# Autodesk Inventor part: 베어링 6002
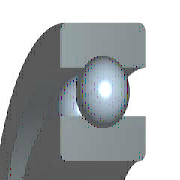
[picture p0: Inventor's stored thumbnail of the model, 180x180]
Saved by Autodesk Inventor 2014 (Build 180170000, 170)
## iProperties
Created: 2012-02
Part Number: 베어링 6002
Material: 강철, 연강
Description: 깊은 그루브 볼 베어링
Document SubType Name: Modeling
Standard: KS B 2023
Designer: mduedu
Standards Organization: KS
Language: ko-KR
Size Designation: 6002 - 15 x 32 x 9
Categories: <MemberInstance><Categories><Category DisplayName="샤프트 부품" InternalName="7f7aeb1f-a693-4053-b835-cee3144e0d98" Mnemonic="SHFT"><Category DisplayName="베어링" Inter
Density: 7.86 g/cm^3
Mass: 29.8124 g
Surface Area: 39.9079 cm^2
Volume: 3.79293 cm^3
Appearance: Pink
IsCustomPart: 1
Author: mduedu
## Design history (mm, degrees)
sketch "스케치" dims "d0" = 4.42 (= -0.26 x WD + 0.26 x BD)
  geometry: L1 (2.29, 11.75)-(6.71, 11.75); L2 (4.5, 11.75)-(4.5, 9.54); L3 (4.5, 11.75)-(4.5, 13.96); L4 (2.858, 10.271)-(0, 10.271); L5 (0, 7.5)-(9, 7.5); L6 (2.858, 13.229)-(0, 13.229); L7 (0, 16)-(9, 16); L8 (9, 7.5)-(9, 10.271); L9 (6.142, 10.271)-(9, 10.271); L10 (6.142, 13.229)-(9, 13.229); L11 (9, 16)-(9, 13.229); L12 (-1.4, 0)-(8.4, 0) reference; L13 (0, -0.3)-(0, 5.3) reference
  constraints: 22 end point, 4 point on line, 2 collinear, 2 perpendicular, 2 symmetric about line, 1 midpoint, 1 parallel, 14 other
  dimensions: "d9" = 15 diameter of L5 L12 (= WD); "d11" = 32 diameter of L7 L12 (= BD); "d12" = 9 distance between parallel lines of L8 L13 (= KB); "d13" = 20.542 diameter of L9 L12 (= 0.326 x BD + 0.674 x WD)
revolve "본체" stored, may be unused: angle "d6" = 90 deg
revolve "볼" stored, may be unused: angle "d7" = 90 deg
pattern_circular "IDS_ARRAYBALL[SIMPL:T]" dims angle "d3" = 360 deg
body "Solid1"
fillet "모깎기1" dims "d1" = 0.3 (= KRS)
other parameters: "WD" = 15 [user parameter; used in 5 equation terms], "BD" = 32 [user parameter; used in 5 equation terms], "KB" = 9 [user parameter; used in 1 equation term], "KRS" = 0.3 [user parameter; used in 1 equation term], "d4" = 0, "d5" = 0, "d8" = 0, "d14" = 0, "d15" = 0, "BBA" = 0 [user parameter], "BC0" = 2850000 [user parameter], "BC" = 5590000 [user parameter], "BR" = 16 (= 0.5 x BD) [user parameter], "WR" = 7.5 (= 0.5 x WD) [user parameter]
